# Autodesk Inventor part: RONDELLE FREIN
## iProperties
Created: 2004-11
Part Number: RONDELLE FREIN
Document SubType Name: Modeling
Designer: Bruno
Manufacturer: Standard
Standards Organization: Custom
Author: Bruno
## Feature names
1. Base1
